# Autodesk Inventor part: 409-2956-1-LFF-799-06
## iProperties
Created: 2010-11
Part Number: 409-2956-1-LFF-799-06
Material: 3/4" OD TUBE - SS
Document SubType Name: Modeling
Designer: S. Boerckel
Engineer: Steve Boerckel
Mass: 340.704 g
Surface Area: 512.603 cm^2
Volume: 42.1664 cm^3
Density: 8.08 g/cm^3
Description: DRAIN TUBING
Length: 18.395 in
Author: S. Boerckel
Revision Number: 0
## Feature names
1. Sweep2
